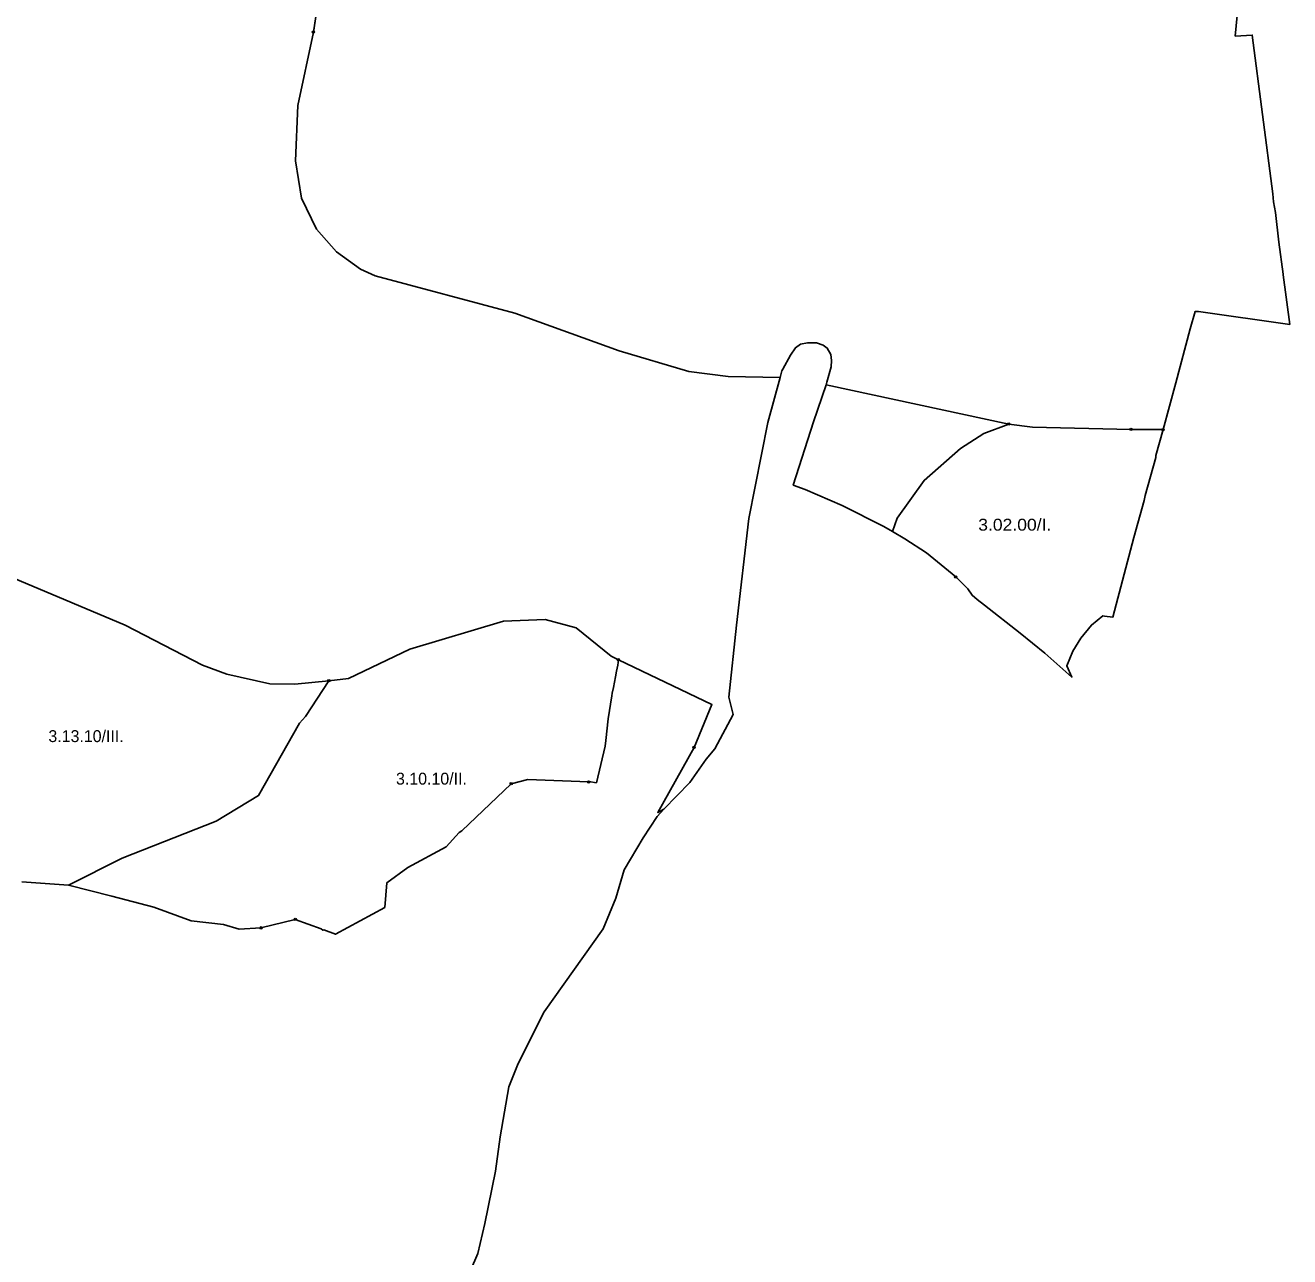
# Model space of a CAD drawing. Extents: x -650455 to -642254, y -1075222 to -1066610.
# Drawn here: x -648146 to -647085, y -1074176 to -1073142 of the extents above; entities that cross this region are included whole.
import ezdxf
from ezdxf.enums import TextEntityAlignment as Align

# ---------------------------------------------------------------- set-up
doc = ezdxf.new("R2010")
doc.units = 0
doc.header["$LTSCALE"] = 4
doc.header["$PDMODE"] = 32
doc.header["$PDSIZE"] = 2
for name, color, linetype, lineweight in [('1', 7, 'Continuous', 25), ('11', 7, 'Continuous', 13), ('12', 7, 'Continuous', 13), ('13', 7, 'Continuous', 13)]:
    doc.layers.add(name, color=color, linetype=linetype, lineweight=lineweight)
doc.layers.add('2', color=7, linetype='Continuous')

msp = doc.modelspace()

# ---------------------------------------------------------------- linework, layer by layer
at = {"layer": '1'}
for points in [[(-647889.5, -1073048.5), (-647904.5, -1073148.001), (-647917.5, -1073209.501), (-647919.5, -1073256), (-647914.5, -1073287.5), (-647902, -1073313.501), (-647885, -1073332.5), (-647865, -1073347.001), (-647852.5, -1073352.5), (-647735.5, -1073384), (-647648, -1073415.501), (-647589.5, -1073433), (-647556.5, -1073437), (-647512.745, -1073437.818), (-647523.009, -1073475.688), (-647539.149, -1073556.382), (-647549.295, -1073645.879)], [(-647489.976, -1073408.948), (-647495.601, -1073410.03), (-647499.927, -1073413.062), (-647504.254, -1073419.123), (-647510.484, -1073430.899), (-647511.276, -1073432.397), (-647512.745, -1073437.818), (-647556.5, -1073437), (-647589.5, -1073433), (-647648, -1073415.501), (-647735.5, -1073384), (-647852.5, -1073352.5), (-647865, -1073347.001), (-647885, -1073332.5), (-647902, -1073313.501), (-647914.5, -1073287.5), (-647919.5, -1073256), (-647917.5, -1073209.501), (-647904.5, -1073148.001), (-647889.5, -1073048.5)], [(-647122.941, -1073068.189), (-647130.088, -1073142.652), (-647130.89, -1073151.357), (-647116.626, -1073150.512), (-647099.269, -1073283.721), (-647098.705, -1073290.495), (-647097.153, -1073299.526), (-647094.33, -1073324.363), (-647090.661, -1073351.173), (-647090.847, -1073351.875), (-647085.223, -1073393.44), (-647161.783, -1073382.641), (-647164.605, -1073382.642), (-647168.838, -1073397.177), (-647180.691, -1073442.334), (-647191.543, -1073481.728), (-647218.5, -1073481.5), (-647301, -1073479.501), (-647321, -1073477), (-647474.308, -1073444.149), (-647473.536, -1073441.853), (-647470.074, -1073429.081), (-647469.642, -1073423.67), (-647470.291, -1073418.689), (-647473.319, -1073413.278), (-647476.78, -1073410.896), (-647482.189, -1073408.948), (-647489.976, -1073408.948)], [(-648196, -1073589.501), (-648062.5, -1073646.001), (-647997.5, -1073679.5), (-647977, -1073687.001), (-647941, -1073695.001), (-647920, -1073695.5), (-647891.5, -1073692.5), (-647911, -1073722.501), (-647916.03, -1073728.11), (-647950.443, -1073788.764), (-647986, -1073810.5), (-648065, -1073841.5), (-648110, -1073864.001), (-648149.105, -1073861.45)], [(-647549.295, -1073645.879), (-647555.929, -1073706.229), (-647552.115, -1073720.775), (-647567.708, -1073749.687), (-647574.926, -1073758.495), (-647588.524, -1073777.822), (-647610.282, -1073800.427), (-647615.5, -1073803.001), (-647585, -1073748.5), (-647570, -1073712.5), (-647648.56, -1073674.85), (-647654.5, -1073672), (-647684, -1073648), (-647710, -1073641.001), (-647745, -1073642.501), (-647823.5, -1073666.001), (-647875, -1073690.501), (-647891.5, -1073692.5), (-647920, -1073695.5), (-647941, -1073695.001), (-647977, -1073687.001), (-647997.5, -1073679.5), (-648062.5, -1073646.001), (-648196, -1073589.501)], [(-647875, -1073690.501), (-647823.5, -1073666.001), (-647745, -1073642.501), (-647710, -1073641.001), (-647684, -1073648), (-647654.5, -1073672), (-647648.56, -1073674.85)], [(-647648.56, -1073674.85), (-647649.01, -1073679.36), (-647650.01, -1073684.42), (-647650.96, -1073689.171), (-647652.75, -1073698.15), (-647653.73, -1073703.07), (-647654.08, -1073705.051), (-647657.12, -1073724.42), (-647659.07, -1073742.58), (-647659.58, -1073747.371), (-647666.96, -1073778.14), (-647673.428, -1073777.101), (-647673.5, -1073777.5), (-647724.5, -1073775.501), (-647738.5, -1073779.001), (-647780, -1073818.5), (-647782.22, -1073819.921), (-647793.19, -1073831.831), (-647825.191, -1073849.38), (-647842.74, -1073862.31), (-647844.57, -1073882.821), (-647885.89, -1073905.24), (-647895.712, -1073901.66), (-647896.5, -1073902), (-647897.999, -1073900.817), (-647919.64, -1073892.921), (-647948.47, -1073899.97), (-647966.84, -1073901.04), (-647980, -1073897.156), (-648007, -1073894), (-648038.5, -1073882.5), (-648073.5, -1073873.501), (-648110, -1073864.001), (-648065, -1073841.5), (-647986, -1073810.5), (-647950.443, -1073788.764), (-647916.03, -1073728.11), (-647911, -1073722.501), (-647891.5, -1073692.5), (-647875, -1073690.501)], [(-647966.84, -1073901.04), (-647948.47, -1073899.97), (-647919.64, -1073892.921), (-647897.999, -1073900.817), (-647896.5, -1073902), (-647895.712, -1073901.66), (-647885.89, -1073905.24), (-647844.57, -1073882.821), (-647842.74, -1073862.31), (-647825.191, -1073849.38), (-647793.19, -1073831.831), (-647782.22, -1073819.921), (-647780, -1073818.5), (-647738.5, -1073779.001), (-647724.5, -1073775.501), (-647673.5, -1073777.5), (-647673.428, -1073777.101), (-647666.96, -1073778.14), (-647659.58, -1073747.371), (-647659.07, -1073742.58), (-647657.12, -1073724.42), (-647654.08, -1073705.051), (-647653.73, -1073703.07), (-647652.75, -1073698.15), (-647650.96, -1073689.171), (-647650.01, -1073684.42), (-647649.01, -1073679.36), (-647648.56, -1073674.85), (-647570, -1073712.5), (-647585, -1073748.5), (-647615.5, -1073803.001), (-647610.282, -1073800.427)], [(-647610.282, -1073800.427), (-647615.988, -1073806.355), (-647627.78, -1073824.409), (-647643.625, -1073851.181), (-647650.667, -1073875.134), (-647661.23, -1073900.849), (-647710.758, -1073970.544), (-647732.586, -1074013.768), (-647740.418, -1074033.399), (-647747.813, -1074075.318), (-647751.686, -1074104.202), (-647760.489, -1074148.235), (-647766.475, -1074173.244), (-647779.502, -1074203.89)], [(-648149.105, -1073861.45), (-648110, -1073864.001), (-648073.5, -1073873.501), (-648038.5, -1073882.5), (-648007, -1073894), (-647980, -1073897.156), (-647966.84, -1073901.04)]]:
    msp.add_lwpolyline(points, dxfattribs=at)
for points in [[(-647414.5, -1073556.001), (-647418.548, -1073567.245), (-647425.815, -1073563.032), (-647460.652, -1073545.317), (-647491.837, -1073531.962), (-647501.823, -1073528.217), (-647484.785, -1073475.301), (-647474.308, -1073444.149), (-647321, -1073477), (-647342, -1073485), (-647361.5, -1073497.5), (-647392, -1073524.501)], [(-647215.97, -1073572.157), (-647233.622, -1073639.105), (-647240.559, -1073638.303), (-647242.059, -1073638.13), (-647251.611, -1073645.862), (-647260.601, -1073656.828), (-647267.344, -1073667.795), (-647272.175, -1073680.016), (-647267.977, -1073689.516), (-647290.737, -1073669.383), (-647311.373, -1073652.56), (-647341.395, -1073629.138), (-647347.521, -1073624.289), (-647351.617, -1073620.751), (-647355.299, -1073615.471), (-647365.413, -1073605.349), (-647390.136, -1073585.104), (-647408.116, -1073573.294), (-647418.548, -1073567.245), (-647414.5, -1073556.001), (-647392, -1073524.501), (-647361.5, -1073497.5), (-647342, -1073485), (-647321, -1073477), (-647301, -1073479.501), (-647218.5, -1073481.5), (-647191.543, -1073481.728), (-647197.484, -1073503.293), (-647197.625, -1073504.988), (-647206.515, -1073536.879), (-647207.362, -1073541.112)]]:
    msp.add_lwpolyline(points, close=True, dxfattribs=at)
at = {"layer": '11'}
for points in [[(-647339.5, -1072889.001), (-647407.174, -1072877.482), (-647467.805, -1073000), (-647452.469, -1073000), (-647459.21, -1073004.071), (-647476.435, -1073003.416), (-647893.795, -1073076.991), (-647904.5, -1073148.001), (-647917.5, -1073209.501), (-647919.5, -1073256), (-647914.5, -1073287.5), (-647902, -1073313.501), (-647885, -1073332.5), (-647865, -1073347.001), (-647852.5, -1073352.5), (-647735.5, -1073384), (-647648, -1073415.501), (-647589.5, -1073433)], [(-647191.543, -1073481.728), (-647180.691, -1073442.334), (-647168.838, -1073397.177), (-647164.605, -1073382.642), (-647161.783, -1073382.641), (-647085.223, -1073393.44), (-647090.847, -1073351.875), (-647090.661, -1073351.173), (-647094.33, -1073324.363), (-647097.153, -1073299.526), (-647098.705, -1073290.495), (-647099.269, -1073283.721), (-647116.626, -1073150.512), (-647130.89, -1073151.357), (-647130.088, -1073142.652), (-647122.941, -1073068.189)], [(-647589.5, -1073433), (-647556.5, -1073437), (-647512.745, -1073437.818), (-647511.276, -1073432.397), (-647510.484, -1073430.899), (-647504.254, -1073419.123), (-647499.927, -1073413.062), (-647495.601, -1073410.03), (-647489.976, -1073408.948), (-647482.189, -1073408.948), (-647476.78, -1073410.896), (-647473.319, -1073413.278), (-647470.291, -1073418.689), (-647469.642, -1073423.67), (-647470.074, -1073429.081), (-647473.536, -1073441.853), (-647474.308, -1073444.149), (-647321, -1073477)], [(-647218.5, -1073481.5), (-647301, -1073479.501), (-647321, -1073477), (-647342, -1073485), (-647361.5, -1073497.5), (-647392, -1073524.501), (-647414.5, -1073556.001), (-647418.548, -1073567.245), (-647408.116, -1073573.294), (-647390.136, -1073585.104), (-647365.413, -1073605.349)], [(-647365.413, -1073605.349), (-647355.299, -1073615.471), (-647351.617, -1073620.751), (-647347.521, -1073624.289), (-647341.395, -1073629.138), (-647311.373, -1073652.56), (-647290.737, -1073669.383), (-647267.977, -1073689.516), (-647272.175, -1073680.016), (-647267.344, -1073667.795), (-647260.601, -1073656.828), (-647251.611, -1073645.862), (-647242.059, -1073638.13), (-647240.559, -1073638.303), (-647233.622, -1073639.105), (-647215.97, -1073572.157), (-647207.362, -1073541.112), (-647206.515, -1073536.879), (-647197.625, -1073504.988), (-647197.484, -1073503.293), (-647191.543, -1073481.728), (-647218.5, -1073481.5)], [(-647321, -1073477), (-647301, -1073479.501), (-647218.5, -1073481.5), (-647191.543, -1073481.728)]]:
    msp.add_lwpolyline(points, dxfattribs=at)
for p in [(-647321, -1073477), (-647218.5, -1073481.5), (-647191.543, -1073481.728), (-647365.413, -1073605.349)]:
    msp.add_point(p, dxfattribs=at)
at = {"layer": '12'}
msp.add_line((-647948.47, -1073899.97), (-647919.64, -1073892.921), dxfattribs=at)
for points in [[(-647648.56, -1073674.85), (-647654.5, -1073672), (-647684, -1073648), (-647710, -1073641.001), (-647745, -1073642.501), (-647823.5, -1073666.001), (-647875, -1073690.501), (-647891.5, -1073692.5)], [(-647673.5, -1073777.5), (-647673.428, -1073777.101), (-647666.96, -1073778.14), (-647659.58, -1073747.371), (-647659.07, -1073742.58), (-647657.12, -1073724.42), (-647654.08, -1073705.051), (-647653.73, -1073703.07), (-647652.75, -1073698.15), (-647650.96, -1073689.171), (-647650.01, -1073684.42), (-647649.01, -1073679.36), (-647648.56, -1073674.85)], [(-647891.5, -1073692.5), (-647911, -1073722.501), (-647916.03, -1073728.11), (-647950.443, -1073788.764), (-647986, -1073810.5), (-648065, -1073841.5), (-648110, -1073864.001), (-648073.5, -1073873.501), (-648038.5, -1073882.5), (-648007, -1073894), (-647980, -1073897.156), (-647966.84, -1073901.04), (-647948.47, -1073899.97)], [(-647738.5, -1073779.001), (-647724.5, -1073775.501), (-647673.5, -1073777.5)], [(-647919.64, -1073892.921), (-647897.999, -1073900.817), (-647896.5, -1073902), (-647895.712, -1073901.66), (-647885.89, -1073905.24), (-647844.57, -1073882.821), (-647842.74, -1073862.31), (-647825.191, -1073849.38), (-647793.19, -1073831.831), (-647782.22, -1073819.921), (-647780, -1073818.5), (-647738.5, -1073779.001)]]:
    msp.add_lwpolyline(points, dxfattribs=at)
for p in [(-647648.56, -1073674.85), (-647891.5, -1073692.5), (-647738.5, -1073779.001), (-647673.5, -1073777.5), (-647919.64, -1073892.921), (-647948.47, -1073899.97)]:
    msp.add_point(p, dxfattribs=at)
at = {"layer": '13'}
for points in [[(-647904.5, -1073148.001), (-647893.795, -1073076.991)], [(-647585, -1073748.5), (-647615.5, -1073803.001), (-647610.282, -1073800.427), (-647588.524, -1073777.822), (-647574.926, -1073758.495), (-647567.708, -1073749.687), (-647552.115, -1073720.775), (-647555.929, -1073706.229), (-647549.295, -1073645.879), (-647539.149, -1073556.382), (-647523.009, -1073475.688), (-647512.745, -1073437.818), (-647556.5, -1073437), (-647589.5, -1073433), (-647648, -1073415.501), (-647735.5, -1073384), (-647852.5, -1073352.5), (-647865, -1073347.001), (-647885, -1073332.5), (-647902, -1073313.501), (-647914.5, -1073287.5), (-647919.5, -1073256), (-647917.5, -1073209.501), (-647904.5, -1073148.001)], [(-648255, -1073570), (-648196, -1073589.501), (-648062.5, -1073646.001), (-647997.5, -1073679.5), (-647977, -1073687.001), (-647941, -1073695.001), (-647920, -1073695.5), (-647891.5, -1073692.5), (-647875, -1073690.501), (-647823.5, -1073666.001), (-647745, -1073642.501), (-647710, -1073641.001), (-647684, -1073648), (-647654.5, -1073672), (-647648.56, -1073674.85), (-647570, -1073712.5), (-647585, -1073748.5)], [(-648149.105, -1073861.45), (-648110, -1073864.001), (-648065, -1073841.5), (-647986, -1073810.5), (-647950.443, -1073788.764), (-647916.03, -1073728.11), (-647911, -1073722.501), (-647891.5, -1073692.5), (-647920, -1073695.5), (-647941, -1073695.001), (-647977, -1073687.001), (-647997.5, -1073679.5), (-648062.5, -1073646.001), (-648196, -1073589.501)]]:
    msp.add_lwpolyline(points, dxfattribs=at)
for p in [(-647904.5, -1073148.001), (-647585, -1073748.5)]:
    msp.add_point(p, dxfattribs=at)

# ---------------------------------------------------------------- texts
at = {"layer": '2', "width": 1.1}
msp.add_text('3.02.00/I.', height=10, dxfattribs=at).set_placement((-647315.927, -1073566.523), align=Align.CENTER)
at = {"layer": '2'}
for s, p in [('3.13.10/III.', (-648095.245, -1073744.022)), ('3.10.10/II.', (-647805.409, -1073779.732))]:
    msp.add_text(s, height=10, dxfattribs=at).set_placement(p, align=Align.CENTER)

doc.saveas('drawing.dxf')
